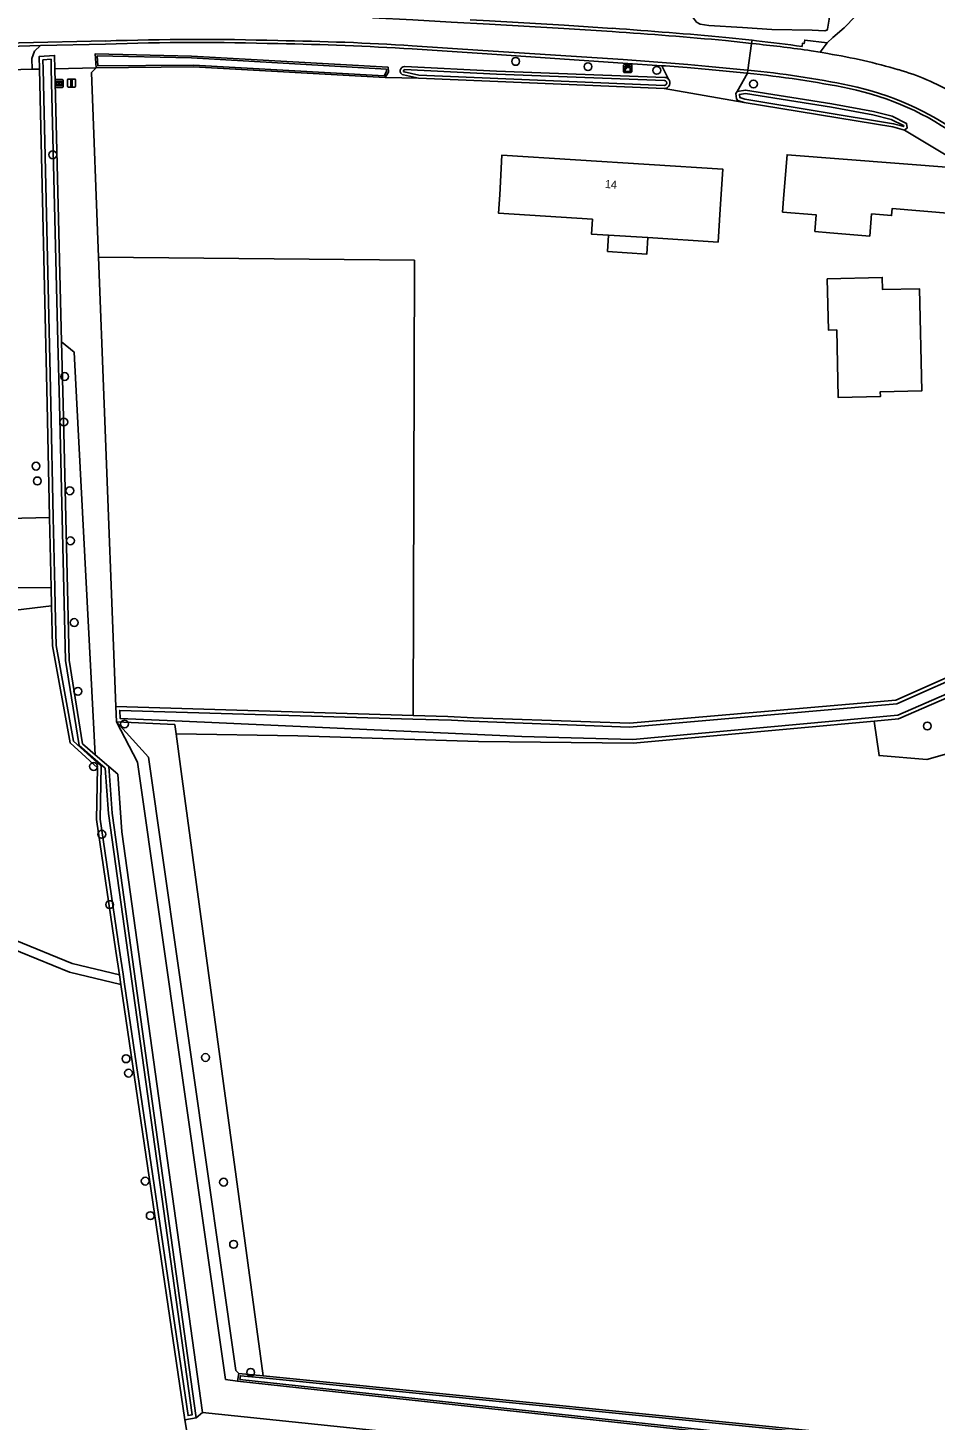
# Model space of a CAD drawing. Extents: x 162515 to 163909, y 388494 to 389773.
# Drawn here: x 162768.7 to 162882.1, y 388873 to 389047 of the extents above; entities that cross this region are included whole.
import ezdxf

# ---------------------------------------------------------------- set-up
doc = ezdxf.new("R2010")
doc.units = 0
for name, color, linetype in [('IMGEO_Afsluitpaal', 7, 'Continuous'), ('IMGEO_Boom', 7, 'Continuous'), ('IMGEO_Erf', 7, 'Continuous'), ('IMGEO_Grasland_agrarisch', 7, 'Continuous'), ('IMGEO_Grasland_overig', 7, 'Continuous'), ('IMGEO_Groenvoorziening', 7, 'Continuous'), ('IMGEO_Hek', 7, 'Continuous'), ('IMGEO_Houtwal', 7, 'Continuous'), ('IMGEO_Informatiebord', 7, 'Continuous'), ('IMGEO_Kast', 7, 'Continuous'), ('IMGEO_Loofbos', 7, 'Continuous'), ('IMGEO_Pand', 7, 'Continuous'), ('IMGEO_Pand_nummerreeks', 7, 'Continuous'), ('IMGEO_Rijbaan_lokaal_gesloten', 7, 'Continuous'), ('IMGEO_Rijbaan_lokaal_halfverhard', 7, 'Continuous'), ('IMGEO_Rijbaan_lokaal_open', 7, 'Continuous'), ('IMGEO_Voetpad_halfverhard', 7, 'Continuous'), ('IMGEO_Waterloop', 7, 'Continuous')]:
    doc.layers.add(name, color=color, linetype=linetype)

msp = doc.modelspace()

# ---------------------------------------------------------------- linework, layer by layer
at = {"layer": 'IMGEO_Afsluitpaal'}
for p, q in [((162773.67, 389039.67), (162773.67, 389040.47)), ((162773.67, 389040.47), (162773.67, 389039.67)), ((162773.77, 389040.57), (162774.56, 389040.57)), ((162774.56, 389040.57), (162773.77, 389040.57)), ((162774.66, 389040.47), (162774.66, 389039.67)), ((162774.66, 389039.67), (162774.66, 389040.47)), ((162774.56, 389039.57), (162773.77, 389039.57)), ((162773.77, 389039.57), (162774.56, 389039.57))]:
    msp.add_line(p, q, dxfattribs=at)
msp.add_lwpolyline([(162774.09, 389040.44), (162774.24, 389040.44), (162774.24, 389039.69), (162774.09, 389039.69), (162774.09, 389040.44)], dxfattribs=at)
for centre, start, end in [((162773.77, 389040.47), 90, 180), ((162773.77, 389040.47), 90, 180), ((162774.56, 389040.47), 0, 90), ((162774.56, 389040.47), 360, 90), ((162773.77, 389039.67), 180, 270), ((162773.77, 389039.67), 180, 270), ((162774.56, 389039.67), 270, 0), ((162774.56, 389039.67), 270, 0)]:
    msp.add_arc(centre, 0.1, start, end, dxfattribs=at)
at = {"layer": 'IMGEO_Boom'}
for centre in [(162829.66, 389042.77), (162838.7, 389042.12), (162847.29, 389041.65), (162859.37, 389039.95), (162771.83, 389031.1), (162773.32, 389003.39), (162773.21, 388997.71), (162769.74, 388992.2), (162769.9, 388990.35), (162773.96, 388989.12), (162774.04, 388982.87), (162774.51, 388972.65), (162774.97, 388964.06), (162780.8, 388959.98), (162881.08, 388959.72), (162776.93, 388954.67), (162777.96, 388946.2), (162778.94, 388937.41), (162780.99, 388918.15), (162790.91, 388918.31), (162781.3, 388916.35), (162783.38, 388902.86), (162793.17, 388902.72), (162784.01, 388898.54), (162794.42, 388894.96), (162796.56, 388878.96)]:
    msp.add_circle(centre, 0.489, dxfattribs=at)
at = {"layer": 'IMGEO_Erf'}
for points in [[(162771.44, 388985.76), (162771.12, 389000), (162770.17, 389041.8)], [(162813.37, 389040.74), (162789.42, 389042.09), (162777.27, 389041.97)], [(162848.2, 389039.38), (162817.5, 389040.67)], [(162878.25, 389034.16), (162876.77, 389034.59), (162858.21, 389037.64)], [(162816.85, 388961.05), (162821.19, 388960.92), (162824.39, 388960.76), (162843.87, 388960.07), (162877.14, 388962.94), (162916.43, 388980.39), (162904.76, 389000), (162888.66, 389027.91)]]:
    msp.add_lwpolyline(points, dxfattribs=at)
at = {"layer": 'IMGEO_Grasland_agrarisch'}
for points in [[(162777.55, 389018.32), (162817.01, 389017.92), (162816.85, 388961.05)], [(162816.85, 388961.05), (162779.72, 388962.15)], [(162787.23, 388958.74), (162802.44, 388958.48), (162825, 388957.81), (162844.33, 388957.58), (162874.43, 388960.34)], [(162787.23, 388958.74), (162787.87, 388954.04), (162798.1, 388878.51)], [(162798.1, 388878.51), (162875.43, 388870.78), (162959.49, 388857.47)]]:
    msp.add_lwpolyline(points, dxfattribs=at)
at = {"layer": 'IMGEO_Grasland_overig'}
for points in [[(162772.1, 389041.84), (162777.27, 389041.97)], [(162772.92, 389007.73), (162772.1, 389041.84)], [(162777.27, 389041.97), (162776.65, 389041.37), (162777.55, 389018.32)], [(162857.31, 389039.01), (162858.37, 389039.19), (162869.17, 389037.46), (162874.34, 389036.52), (162876.71, 389035.93), (162878.49, 389035.02), (162878.57, 389034.46), (162878.25, 389034.16)], [(162878.25, 389034.16), (162888.66, 389027.91)], [(162779.72, 388962.15), (162778.26, 389000), (162777.55, 389018.32)], [(162772.92, 389007.73), (162774.5, 389006.45), (162774.84, 389000), (162777.14, 388956.13)], [(162771.63, 388977.03), (162759.18, 388976.94), (162753.18, 388975.82), (162748.59, 388977.36), (162730.5, 388976.95), (162720.37, 388977.67), (162713.87, 388982.43)], [(162874.43, 388960.34), (162877.49, 388960.62), (162916.5, 388977.59), (162919.38, 388978.26), (162919.52, 388978.29)], [(162771.63, 388977.03), (162771.68, 388974.74)], [(162969.72, 388963.11), (162943.58, 388965.98), (162934.15, 388968.56), (162924.89, 388971.24), (162921.31, 388972.48), (162913.72, 388966.33), (162905.08, 388967.36), (162899.05, 388963.63), (162890.42, 388958.22), (162881.01, 388955.53), (162875.05, 388956.02), (162874.43, 388960.34)], [(162779.72, 388962.15), (162779.79, 388960.24)], [(162794.92, 388877.85), (162793.42, 388878.08), (162782.43, 388955.21), (162779.79, 388960.24)], [(162778.83, 388954.66), (162777.14, 388956.13)], [(162778.83, 388954.66), (162779.96, 388953.69), (162780.45, 388946.5), (162790.55, 388873.95)], [(162794.92, 388877.85), (162874.96, 388869.14), (162959.02, 388855.6)]]:
    msp.add_lwpolyline(points, dxfattribs=at)
at = {"layer": 'IMGEO_Groenvoorziening'}
for points in [[(162868.3, 389048.82), (162868.62, 389048.69), (162868.76, 389048.46), (162868.82, 389048.05), (162868.63, 389046.8), (162868.54, 389046.66), (162868.27, 389046.58), (162866.71, 389046.67), (162861.65, 389046.77), (162858, 389046.99), (162853.78, 389047.27), (162852.7, 389047.42), (162852.25, 389047.68), (162851.77, 389048.36), (162851.88, 389049.72), (162852.39, 389050.16)], [(162770.17, 389041.8), (162770.14, 389043.39), (162772.06, 389043.51), (162772.1, 389041.84)], [(162777.27, 389041.97), (162777.14, 389043.72), (162789.15, 389043.43), (162813.72, 389042.04), (162813.78, 389041.44), (162813.37, 389040.74)], [(162769.26, 389041.78), (162770.17, 389041.8)], [(162813.37, 389040.74), (162817.5, 389040.67)], [(162817.5, 389040.67), (162815.65, 389041.08)], [(162815.8, 389042.12), (162827.27, 389041.55), (162848.28, 389040.77)], [(162777.14, 388956.13), (162775.53, 388957.51), (162773.88, 388967.97), (162773.11, 389000), (162772.92, 389007.73)], [(162713.87, 388982.43), (162742.1, 388985.07), (162771.44, 388985.76)], [(162771.44, 388985.76), (162771.63, 388977.03)], [(162779.79, 388960.24), (162783.78, 388955.85), (162794.7, 388879.21), (162795.06, 388878.81)], [(162779.79, 388960.24), (162787.08, 388959.91), (162787.23, 388958.74)], [(162789.75, 388873.27), (162779.24, 388948.83), (162778.83, 388954.66)], [(162795.06, 388878.81), (162794.92, 388877.85)], [(162795.06, 388878.81), (162798.1, 388878.51)]]:
    msp.add_lwpolyline(points, dxfattribs=at)
for centre, radius, start, end in [((162815.76, 389041.59), 0.529, 86.7057, 257.6954), ((162848.23, 389040.07), 0.7, 43.2456, 85.2583)]:
    msp.add_arc(centre, radius, start, end, dxfattribs=at)
at = {"layer": 'IMGEO_Hek'}
for points in [[(162774.5, 389006.45), (162774.84, 389000), (162777.14, 388956.13)], [(162779.79, 388960.24), (162783.78, 388955.85), (162794.7, 388879.21)], [(162778.83, 388954.66), (162779.96, 388953.69), (162780.45, 388946.5), (162790.55, 388873.95)], [(162794.7, 388879.21), (162795.06, 388878.81)], [(162879.79, 388864.66), (162790.55, 388873.95)]]:
    msp.add_lwpolyline(points, dxfattribs=at)
at = {"layer": 'IMGEO_Houtwal'}
for points in [[(162790.55, 388873.95), (162789.75, 388873.27)], [(163009.92, 388844.19), (163000, 388845.32), (162979.56, 388847.81), (162879.79, 388864.66), (162790.55, 388873.95)], [(162789.75, 388873.27), (162788.35, 388873.03)]]:
    msp.add_lwpolyline(points, dxfattribs=at)
at = {"layer": 'IMGEO_Informatiebord'}
for p, q in [((162772.12, 389039.61), (162772.12, 389040.41)), ((162772.12, 389040.41), (162772.12, 389039.61)), ((162772.22, 389040.51), (162773.01, 389040.51)), ((162773.01, 389040.51), (162772.22, 389040.51)), ((162773.11, 389040.41), (162773.11, 389039.61)), ((162773.11, 389039.61), (162773.11, 389040.41)), ((162773.01, 389039.51), (162772.22, 389039.51)), ((162772.22, 389039.51), (162773.01, 389039.51))]:
    msp.add_line(p, q, dxfattribs=at)
for points in [[(162772.22, 389040.25), (162773, 389040.25), (162773, 389039.78), (162772.22, 389039.78), (162772.22, 389040.25)], [(162772.28, 389040.18), (162772.28, 389039.85), (162772.56, 389039.85), (162772.56, 389040.06), (162772.66, 389040.06), (162772.66, 389039.85), (162772.94, 389039.85), (162772.94, 389040.18), (162772.66, 389040.18), (162772.66, 389040.1), (162772.56, 389040.1), (162772.56, 389040.18), (162772.28, 389040.18)]]:
    msp.add_lwpolyline(points, dxfattribs=at)
for centre, start, end in [((162772.22, 389040.41), 90, 180), ((162772.22, 389040.41), 90, 180), ((162773.01, 389040.41), 0, 90), ((162773.01, 389040.41), 360, 90), ((162772.22, 389039.61), 180, 270), ((162772.22, 389039.61), 180, 270), ((162773.01, 389039.61), 270, 0), ((162773.01, 389039.61), 270, 0)]:
    msp.add_arc(centre, 0.1, start, end, dxfattribs=at)
at = {"layer": 'IMGEO_Kast'}
for p, q in [((162843.15, 389041.46), (162843.15, 389042.3)), ((162843.15, 389042.3), (162843.15, 389041.46)), ((162843.23, 389042.38), (162844.07, 389042.38)), ((162844.07, 389042.38), (162843.23, 389042.38)), ((162844.15, 389042.31), (162844.15, 389041.47)), ((162844.15, 389041.47), (162844.15, 389042.31)), ((162844.08, 389041.39), (162843.24, 389041.39)), ((162843.24, 389041.39), (162844.08, 389041.39))]:
    msp.add_line(p, q, dxfattribs=at)
for points in [[(162843.35, 389042.18), (162843.95, 389042.18), (162843.95, 389042.09), (162843.35, 389042.09), (162843.35, 389042.18)], [(162843.35, 389042), (162843.95, 389042), (162843.95, 389041.51), (162843.35, 389041.51), (162843.35, 389042)]]:
    msp.add_lwpolyline(points, dxfattribs=at)
msp.add_circle((162843.43, 389041.85), 0.0377, dxfattribs=at)
for centre, start, end in [((162843.23, 389042.31), 92.4484, 184.2845), ((162843.23, 389042.31), 92.4484, 184.2845), ((162844.07, 389042.31), 2.4484, 94.2845), ((162844.07, 389042.31), 2.4484, 94.2845), ((162843.23, 389041.46), 182.4484, 274.2845), ((162843.23, 389041.46), 182.4484, 274.2845), ((162844.07, 389041.46), 272.4484, 4.2845), ((162844.07, 389041.46), 272.4484, 4.2845)]:
    msp.add_arc(centre, 0.0779, start, end, dxfattribs=at)
at = {"layer": 'IMGEO_Loofbos'}
for points in [[(162706.86, 388970.23), (162716.69, 388972.41), (162727.93, 388973.18), (162739.95, 388975), (162750.24, 388972.84), (162767.18, 388974.22), (162771.68, 388974.74)], [(162771.68, 388974.74), (162771.8, 388969.76), (162773.99, 388957.61), (162777.42, 388954.51), (162777.31, 388948.04), (162779.73, 388931.61), (162780.17, 388928.65)], [(162788.35, 388873.03), (162780.35, 388927.41)], [(162788.35, 388873.03), (162788.74, 388870.61), (162799.08, 388869.54)]]:
    msp.add_lwpolyline(points, dxfattribs=at)
at = {"layer": 'IMGEO_Pand'}
for points in [[(162841.27, 389021.06), (162839.13, 389021.2), (162839.25, 389023.04), (162827.53, 389023.79), (162827.66, 389026.08), (162827.94, 389031.07), (162855.52, 389029.31), (162855.21, 389024.32), (162854.94, 389020.19), (162846.18, 389020.75)], [(162867.03, 389021.53), (162867.2, 389023.58), (162863, 389023.94), (162863.17, 389026.12), (162863.56, 389031.1), (162884.55, 389029.46), (162884.11, 389023.77), (162876.68, 389024.39), (162876.61, 389023.5), (162874.12, 389023.71), (162873.89, 389020.95), (162868.91, 389021.37), (162867.03, 389021.53)], [(162846.18, 389020.75), (162846.05, 389018.7), (162841.14, 389019.02), (162841.27, 389021.06)], [(162846.18, 389020.75), (162841.27, 389021.06)], [(162868.59, 389015.62), (162875.46, 389015.77), (162875.5, 389014.26), (162880.1, 389014.36), (162880.38, 389001.6), (162875.21, 389001.49), (162875.23, 389000.88), (162869.96, 389000.76), (162869.77, 389009.21), (162868.73, 389009.19), (162868.59, 389015.62)]]:
    msp.add_lwpolyline(points, dxfattribs=at)
at = {"layer": 'IMGEO_Rijbaan_lokaal_gesloten'}
for points in [[(162841.7, 389046.5), (162835.68, 389046.9), (162826.39, 389047.43), (162821.62, 389047.69), (162816.83, 389047.96), (162811.78, 389048.21)], [(162745.45, 389044.85), (162751.67, 389044.82), (162767.65, 389045.08), (162778.41, 389045.32)], [(162816.72, 389044.73), (162825.54, 389044.15), (162843.08, 389042.99), (162848.49, 389042.58), (162851.15, 389042.37), (162853.8, 389042.14), (162855.97, 389041.94), (162858.15, 389041.72), (162858.68, 389041.67)], [(162859.13, 389045.01), (162855.89, 389045.37)], [(162858.68, 389041.67), (162859.13, 389045.01)], [(162859.71, 389044.95), (162859.13, 389045.01)], [(162867.68, 389043.92), (162866.56, 389044.1)], [(162868.66, 389043.75), (162867.68, 389043.92)]]:
    msp.add_lwpolyline(points, dxfattribs=at)
for centre, radius, start, end in [((162796.46, 388392.88), 655.19, 84.79585, 86.04058), ((162790.01, 388712.84), 332.68, 88.2906, 91.997), ((162795.33, 388702.42), 342.98, 86.4238, 89.2312), ((162841.81, 388872.68), 173.2, 81.7824, 84.0683), ((162856.33, 388969.22), 75.54, 73.7345, 80.6082), ((162848.33, 388929.79), 112.36, 78.1696, 84.715), ((162869.12, 389012.67), 30.25, 59.7395, 73.9437), ((162864.06, 389004.38), 36.13, 53.6844, 78.3393)]:
    msp.add_arc(centre, radius, start, end, dxfattribs=at)
at = {"layer": 'IMGEO_Rijbaan_lokaal_halfverhard'}
for points in [[(162823.96, 389047.96), (162826.41, 389047.83), (162835.71, 389047.3), (162841.73, 389046.9)], [(162855.93, 389045.77), (162859.19, 389045.41)], [(162763.31, 389044.61), (162767.65, 389044.69), (162770.28, 389044.75)], [(162770.28, 389044.75), (162778.42, 389044.93)], [(162816.71, 389044.33), (162825.48, 389043.77), (162843.04, 389042.57), (162847.93, 389042.23)], [(162859.19, 389045.41), (162859.13, 389045.01)], [(162859.75, 389045.35), (162859.19, 389045.41)], [(162868.58, 389045.07), (162865.77, 389045.44), (162865.71, 389045.02), (162865.51, 389045.05), (162865.45, 389044.62)], [(162858.68, 389041.67), (162858.63, 389041.35), (162858.6, 389041.29)], [(162780.17, 388928.65), (162774.27, 388930.05), (162759.98, 388935.89), (162755.76, 388937.15), (162752.38, 388937.21), (162744.35, 388936.06), (162735.9, 388933.72), (162727.74, 388932.58), (162717.28, 388932.34), (162711.59, 388931.69)], [(162780.35, 388927.41), (162773.92, 388928.95), (162759.59, 388934.8), (162755.59, 388936), (162752.45, 388936.05), (162744.59, 388934.93), (162736.14, 388932.59), (162727.84, 388931.42), (162717.36, 388931.19), (162711.78, 388930.55)], [(162780.17, 388928.65), (162780.35, 388927.41)]]:
    msp.add_lwpolyline(points, dxfattribs=at)
for centre, radius, start, end in [((162797.18, 388401.98), 646.46, 84.7862, 86.04864), ((162790.02, 388719.93), 325.21, 88.248, 92.0445), ((162793.03, 388650.14), 394.91, 86.5617, 88.9942), ((162850.02, 388945.55), 100.26, 81.144, 84.4305), ((162845.4, 388909.75), 132.21, 78.6992, 84.2714), ((162863.8, 389003.95), 36.23, 53.7471, 78.0279)]:
    msp.add_arc(centre, radius, start, end, dxfattribs=at)
at = {"layer": 'IMGEO_Rijbaan_lokaal_open'}
for points in [[(162873.08, 389049.44), (162872.13, 389048.41), (162870.71, 389046.98), (162869.3, 389045.74), (162868.58, 389045.07)], [(162867.68, 389043.92), (162868.44, 389044.94), (162868.58, 389045.07)], [(162847.93, 389042.23), (162848.74, 389040.55)], [(162858.6, 389041.29), (162858.12, 389041.34), (162855.95, 389041.57), (162853.78, 389041.77), (162851.08, 389042), (162848.38, 389042.2), (162847.93, 389042.23)], [(162857.31, 389039.01), (162858.6, 389041.29)], [(162848.2, 389039.38), (162858.21, 389037.64)], [(162858.21, 389037.64), (162857.43, 389037.89), (162857.26, 389038.1), (162857.18, 389038.77), (162857.31, 389039.01)]]:
    msp.add_lwpolyline(points, dxfattribs=at)
msp.add_arc((162848.23, 389040.08), 0.698, 268.0051, 43.1143, dxfattribs=at)
at = {"layer": 'IMGEO_Voetpad_halfverhard'}
for points in [[(162769.26, 389041.78), (162769.22, 389043.15), (162769.54, 389044.04), (162770.28, 389044.75)], [(162764.94, 389041.67), (162769.26, 389041.78)]]:
    msp.add_lwpolyline(points, dxfattribs=at)
at = {"layer": 'IMGEO_Waterloop'}
for points in [[(162772.66, 388999.99), (162773.43, 388967.92), (162775.11, 388957.28), (162776.84, 388955.79), (162778.39, 388954.44), (162778.78, 388948.79), (162789.24, 388873.65), (162788.73, 388873.56), (162780.8, 388927.48), (162780.61, 388928.71), (162780.18, 388931.68), (162777.77, 388948.07), (162777.87, 388954.71), (162774.41, 388957.84), (162772.25, 388969.8), (162772.14, 388974.75), (162772.09, 388977.04), (162771.89, 388985.77), (162771.57, 389000.01), (162770.63, 389041.81), (162770.6, 389042.96), (162771.62, 389043.03), (162771.64, 389041.83), (162772.47, 389007.72), (162772.66, 388999.99)], [(162813.51, 389041.82), (162813.54, 389041.49), (162813.24, 389040.98), (162789.43, 389042.32), (162777.48, 389042.2), (162777.39, 389043.48), (162789.15, 389043.2), (162813.51, 389041.82)], [(162848.2, 389039.76), (162817.55, 389041.06), (162815.75, 389041.45), (162815.71, 389041.46)], [(162815.75, 389041.73), (162815.79, 389041.74), (162827.26, 389041.16), (162848.25, 389040.39)], [(162869.1, 389037.05), (162874.26, 389036.11), (162876.57, 389035.53), (162878.11, 389034.75), (162878.13, 389034.63), (162876.86, 389034.99), (162858.3, 389038.04), (162857.67, 389038.25), (162857.66, 389038.27), (162857.61, 389038.64), (162858.38, 389038.76), (162869.1, 389037.05)], [(162889.15, 389027.99), (162905.16, 389000.23), (162917.09, 388980.17), (162877.26, 388962.48), (162843.88, 388959.6), (162823.98, 388960.31), (162821.65, 388960.44), (162816.83, 388960.59), (162780.2, 388961.67), (162780.24, 388960.68), (162787.1, 388960.37), (162830.42, 388958.42), (162844.31, 388958.04), (162877.38, 388961.07)], [(162877.38, 388961.07), (162916.35, 388978.03), (162918.78, 388978.59), (162913.62, 388986.78), (162906.36, 388999.77), (162889.89, 389028.06)], [(162973.84, 388852.35), (162969.08, 388853.95), (162964.1, 388855.13), (162959.05, 388855.85), (162875, 388869.39), (162795.21, 388878.08), (162795.28, 388878.53), (162798.07, 388878.26), (162875.39, 388870.53), (162959.45, 388857.22), (162963.95, 388856.56), (162968.54, 388855.45), (162973, 388853.92)]]:
    msp.add_lwpolyline(points, dxfattribs=at)
for centre, radius, start, end in [((162815.77, 389041.59), 0.143, 96.4578, 248.1612), ((162848.22, 389040.08), 0.313, 265.5434, 86.0244)]:
    msp.add_arc(centre, radius, start, end, dxfattribs=at)

# ---------------------------------------------------------------- texts
at = {"layer": 'IMGEO_Pand_nummerreeks'}
msp.add_text('14', height=1, rotation=356.3388, dxfattribs=at).set_placement((162840.79, 389026.96))

doc.saveas('drawing.dxf')
